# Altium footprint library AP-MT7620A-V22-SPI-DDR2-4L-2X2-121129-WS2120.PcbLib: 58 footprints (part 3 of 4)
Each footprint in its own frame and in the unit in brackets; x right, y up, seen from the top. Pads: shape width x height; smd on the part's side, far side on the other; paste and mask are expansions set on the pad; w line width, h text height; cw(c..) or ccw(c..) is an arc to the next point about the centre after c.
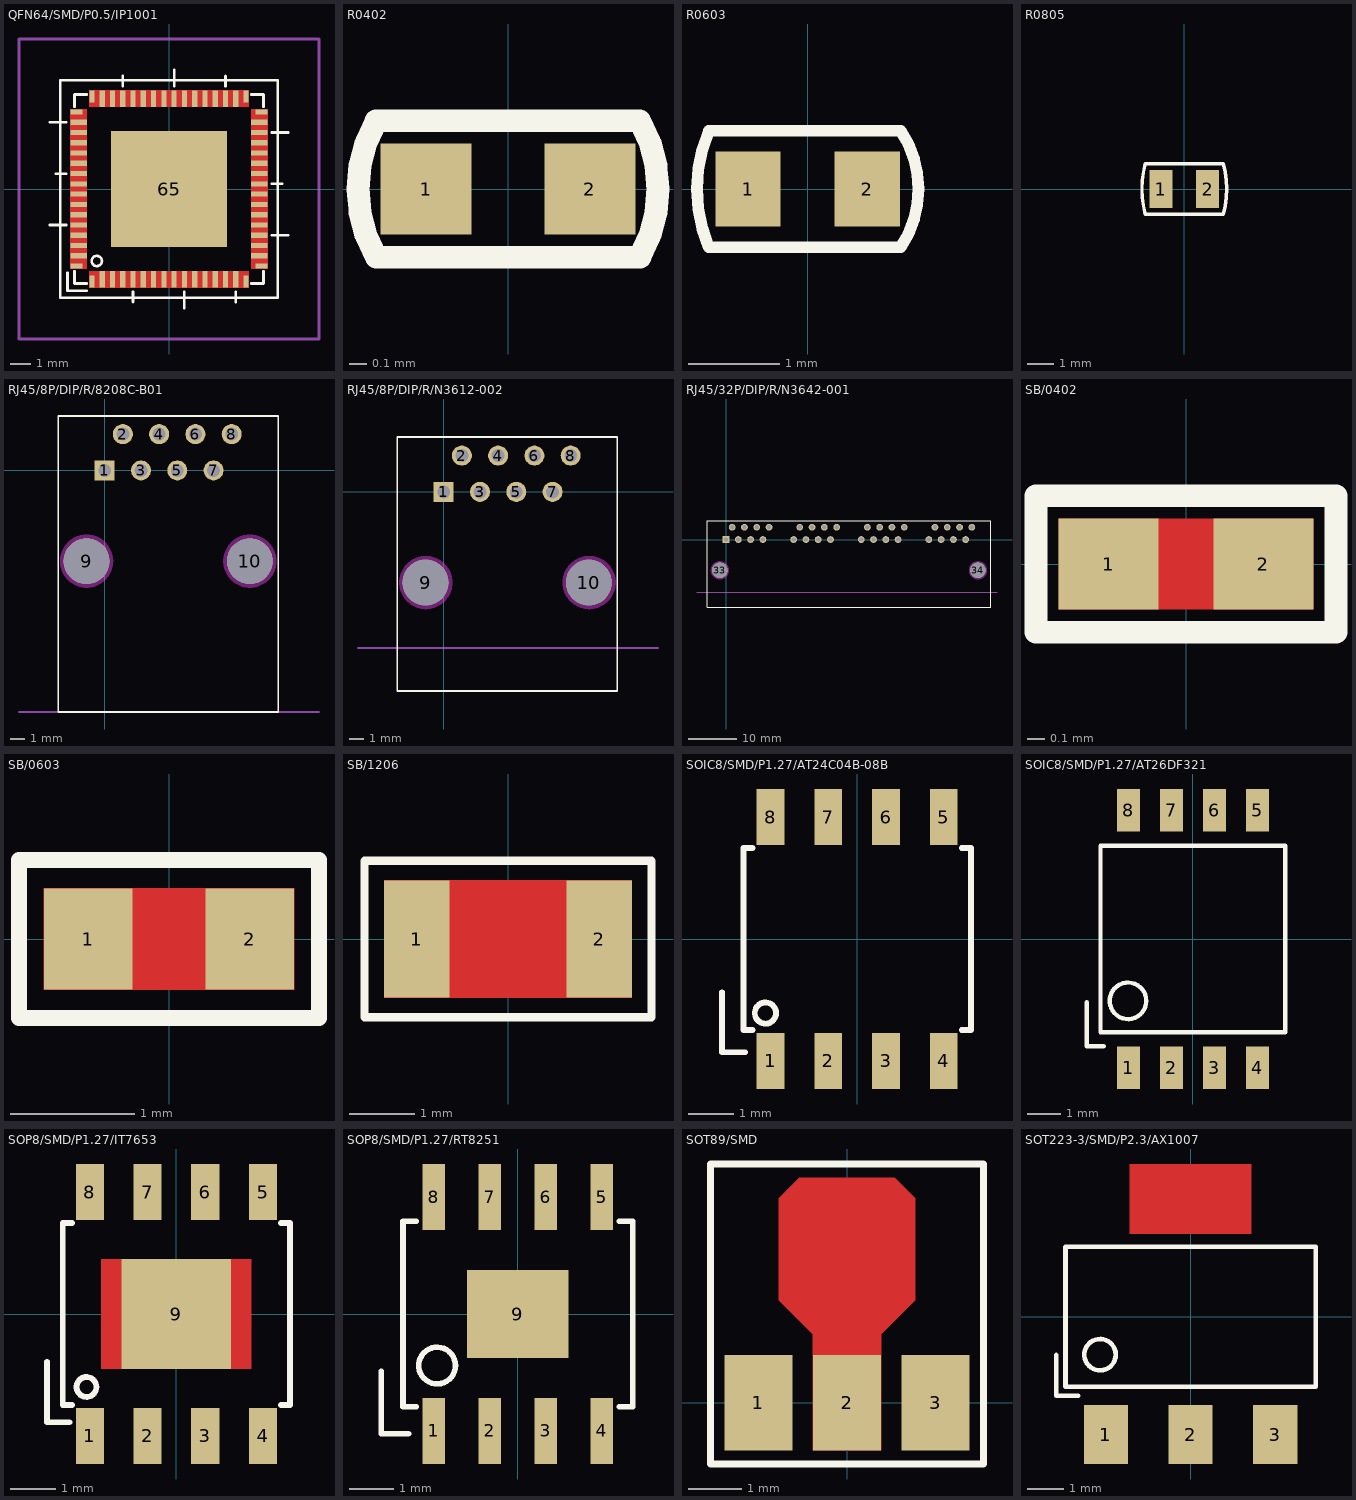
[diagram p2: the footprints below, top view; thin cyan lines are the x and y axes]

## QFN64/SMD/P0.5/IP1001 [mm]
pads (65):
  rect 0.25x0.6 smd: 1(-3.75,-4.5) 16(3.75,-4.5) 33(3.75,4.5) 48(-3.75,4.5)
  rect 0.25x0.8 smd: 2(-3.25,-4.4) 3(-2.75,-4.4) 4(-2.25,-4.4) 5(-1.75,-4.4) 6(-1.25,-4.4) 7(-0.75,-4.4) 8(-0.25,-4.4) 9(0.25,-4.4) 10(0.75,-4.4) 11(1.25,-4.4) 12(1.75,-4.4) 13(2.25,-4.4) 14(2.75,-4.4) 15(3.25,-4.4) 34(3.25,4.4) 35(2.75,4.4) 36(2.25,4.4) 37(1.75,4.4) 38(1.25,4.4) 39(0.75,4.4) 40(0.25,4.4) 41(-0.25,4.4) 42(-0.75,4.4) 43(-1.25,4.4) 44(-1.75,4.4) 45(-2.25,4.4) 46(-2.75,4.4) 47(-3.25,4.4)
  rect 0.6x0.25 smd: 17(4.5,-3.75) 32(4.5,3.75) 49(-4.5,3.75) 64(-4.5,-3.75)
  rect 0.8x0.25 smd: 18(4.4,-3.25) 19(4.4,-2.75) 20(4.4,-2.25) 21(4.4,-1.75) 22(4.4,-1.25) 23(4.4,-0.75) 24(4.4,-0.25) 25(4.4,0.25) 26(4.4,0.75) 27(4.4,1.25) 28(4.4,1.75) 29(4.4,2.25) 30(4.4,2.75) 31(4.4,3.25) 50(-4.4,3.25) 51(-4.4,2.75) 52(-4.4,2.25) 53(-4.4,1.75) 54(-4.4,1.25) 55(-4.4,0.75) 56(-4.4,0.25) 57(-4.4,-0.25) 58(-4.4,-0.75) 59(-4.4,-1.25) 60(-4.4,-1.75) 61(-4.4,-2.25) 62(-4.4,-2.75) 63(-4.4,-3.25)
  rect 5.64x5.64 smd: 65(0,0)
Top Layer:
  pour cut-out: 3.876,4 -3.876,4 -3.876,4.802 3.876,4.802
  pour cut-out: 3.87,-4.794 -3.882,-4.794 -3.882,-3.993 3.87,-3.993
  pour cut-out: 4.798,3.88 4.798,-3.872 3.993,-3.872 3.993,3.88
  pour cut-out: -3.998,3.877 -3.998,-3.88 -4.806,-3.88 -4.806,3.877
Top Overlay:
  circle w0.127: c-3.513,-3.503 r0.25
  lines w0.127: -5.8,-1.75 -5,-1.75 ; -5.8,3.25 -5,3.25 ; -5.5,0.75 -5,0.75 ; -4.939,-4.082 -4.939,-4.956 -4.012,-4.956 ; -4.6,-4 -4.6,-4.6 -4,-4.6 ; -4.6,4 -4.6,4.6 -4,4.6 ; -2.25,5 -2.25,5.5 ; -1.75,-5.5 -1.75,-5 ; 0.25,5 0.25,5.8 ; 0.75,-5.8 0.75,-5 ; 2.75,5 2.75,5.5 ; 3.25,-5.5 3.25,-5 ; 4,-4.6 4.6,-4.6 4.6,-4 ; 4,4.6 4.6,4.6 4.6,4 ; 5,-2.25 5.8,-2.25 ; 5,0.25 5.5,0.25 ; 5,2.75 5.8,2.75 ; -5.3,-5.3 5.3,-5.3 5.3,5.3 -5.3,5.3 -5.3,-5.3
Top Paste:
  region: 0.2,2.57 2.57,2.57 2.57,0.2 0.2,0.2
  region: -2.57,2.57 -0.2,2.57 -0.2,0.2 -2.57,0.2
  region: -2.57,-0.2 -0.2,-0.2 -0.2,-2.57 -2.57,-2.57
  region: 0.2,-0.2 2.57,-0.2 2.57,-2.57 0.2,-2.57
Mechanical 16:
  lines w0.127: -7.3,-7.3 7.3,-7.3 7.3,7.3 -7.3,7.3 -7.3,-7.3

## R0402 [mil]
pads (2):
  rect 20x20 smd: 1(-18,0) 2(18,0)
Top Overlay:
  lines w5: -29.02,14.97 ccw(c-2.88,0) -28.99,-15.02 29,-15 ; -29,15 29,15 cw(c2.88,0) 29.02,-14.97

## R0603 [mil]
pads (2):
  rect 28x32 smd: 1(-25.59,0) 2(25.59,0)
Top Overlay:
  lines w5: -42.5,-25 40,-25 ccw(c2.5,0) 40,25.01 -42.5,25 ; -42.51,-24.97 cw(c16.88,0) -42.47,25.07

## R0805 [mil]
pads (2):
  rect 34x56 smd: 1(-34.45,0) 2(34.45,0)
Top Overlay:
  lines w5: -57.49,-37.53 cw(c80.62,0) -57.49,37.53 ; -57.5,-37.5 57.5,-37.5 ; -57.5,37.5 57.5,37.5 ; 57.47,37.6 cw(c-78.12,0) 57.54,-37.37

## RJ45/8P/DIP/R/8208C-B01 [mm]
pads (10):
  rect 1.4x1.4 / inner round 1.4 / far side rect 1.4x1.4 hole 0.9: 1(0,0)
  round 1.4 hole 0.9: 2(1.27,2.54) 3(2.54,0) 4(3.81,2.54) 5(5.08,0) 6(6.35,2.54) 7(7.62,0) 8(8.89,2.54)
  round 3.2 hole 3.2 unplated: 9(-1.27,-6.35) 10(10.16,-6.35)
Top Overlay:
  lines w0.127: -3.255,-16.9 12.145,-16.9 12.145,3.8 -3.255,3.8 -3.255,-16.9
Keep-Out Layer:
  drawing of 2 lines, arcs and shapes, not listed
Mechanical 16:
  lines w0.127: -6,-16.9 15,-16.9

## RJ45/8P/DIP/R/N3612-002 [mm]
pads (10):
  rect 1.4x1.4 / inner round 1.4 / far side rect 1.4x1.4 hole 0.9: 1(0,0)
  round 1.4 hole 0.9: 2(1.27,2.54) 3(2.54,0) 4(3.81,2.54) 5(5.08,0) 6(6.35,2.54) 7(7.62,0) 8(8.89,2.54)
  round 3.2 hole 3.2 unplated: 9(-1.27,-6.35) 10(10.16,-6.35)
Top Overlay:
  lines w0.127: -3.255,-13.95 12.145,-13.95 12.145,3.85 -3.255,3.85 -3.255,-13.95
Keep-Out Layer:
  drawing of 2 lines, arcs and shapes, not listed
Mechanical 16:
  lines w0.127: -6,-10.922 15,-10.922

## RJ45/32P/DIP/R/N3642-001 [mm]
pads (34):
  rect 1.4x1.4 / inner round 1.4 / far side round 1.4 hole 0.9: 1(0,0)
  round 1.4 hole 0.9: 2(1.27,2.54) 3(2.54,0) 4(3.81,2.54) 5(5.08,0) 6(6.35,2.54) 7(7.62,0) 8(8.89,2.54) 9(13.97,0) 10(15.24,2.54) 11(16.51,0) 12(17.78,2.54) 13(19.05,0) 14(20.32,2.54) 15(21.59,0) 16(22.86,2.54) 17(27.94,0) 18(29.21,2.54) 19(30.48,0) 20(31.75,2.54) 21(33.02,0) 22(34.29,2.54) 23(35.56,0) 24(36.83,2.54) 25(41.91,0) 26(43.18,2.54) 27(44.45,0) 28(45.72,2.54) 29(46.99,0) 30(48.26,2.54) 31(49.53,0) 32(50.8,2.54)
  round 3.2 hole 3.2 unplated: 33(-1.27,-6.35) 34(52.07,-6.35)
Top Overlay:
  lines w0.127: -3.9,-13.95 54.7,-13.95 54.7,3.85 -3.9,3.85 -3.9,-13.95
Keep-Out Layer:
  drawing of 2 lines, arcs and shapes, not listed
Mechanical 16:
  lines w0.127: -6,-10.922 56,-10.922

## SB/0402 [mil]
pads (2):
  rect 22x20 smd: 1(-17,0) 2(17,0)
Top Layer:
  region: -28,10 0,10 0,-10 -28,-10
  region: 28,-10 0,-10 0,10 28,10
Top Overlay:
  lines w5: -33,-15 -33,15 33,15 33,-15 -33,-15

## SB/0603 [mil]
pads (2):
  rect 28x32 smd: 1(-25.59,0) 2(25.59,0)
Top Layer:
  region: 0,16 39.6,16 39.6,-16 0,-16
  region: -39.6,16 0,16 0,-16 -39.6,-16
Top Overlay:
  lines w5: -47.5,-25 47.5,-25 47.5,25 -47.5,25 -47.5,-25

## SB/1206 [mm]
pads (2):
  rect 1x1.8 smd: 1(-1.4,0) 2(1.4,0)
Top Layer:
  region: -1.9,0.9 0,0.9 0,-0.9 -1.9,-0.9
  region: 0,-0.9 1.9,-0.9 1.9,0.9 0,0.9
Top Overlay:
  lines w0.127: -2.2,-1.2 2.2,-1.2 2.2,1.2 -2.2,1.2 -2.2,-1.2

## SOIC8/SMD/P1.27/AT24C04B-08B [mm]
pads (8):
  rect 0.61x1.235 smd: 1(-1.905,-2.68) 2(-0.635,-2.68) 3(0.635,-2.68) 4(1.905,-2.68) 5(1.905,2.68) 6(0.635,2.68) 7(-0.635,2.68) 8(-1.905,2.68)
Top Overlay:
  circle w0.127: c-2.018,-1.628 r0.233
  lines w0.127: -2.972,-1.168 -2.972,-2.489 -2.464,-2.489 ; -2.3,-2 -2.5,-2 -2.5,2 -2.3,2 ; 2.3,-2 2.5,-2 2.5,2 2.3,2

## SOIC8/SMD/P1.27/AT26DF321 [mm]
pads (8):
  rect 0.68x1.25 smd: 1(-1.905,-3.805) 2(-0.635,-3.805) 3(0.635,-3.805) 4(1.905,-3.805) 5(1.905,3.805) 6(0.635,3.805) 7(-0.635,3.805) 8(-1.905,3.805)
Top Overlay:
  circle w0.127: c-1.915,-1.826 r0.541
  lines w0.127: -3.13,-1.867 -3.13,-3.167 -2.63,-3.167 ; -2.725,-2.75 2.725,-2.75 2.725,2.75 -2.725,2.75 -2.725,-2.75

## SOP8/SMD/P1.27/IT7653 [mm]
pads (9):
  rect 0.62x1.235 smd: 1(-1.905,-2.682) 2(-0.635,-2.682) 3(0.635,-2.682) 4(1.905,-2.682) 5(1.905,2.682) 6(0.635,2.682) 7(-0.635,2.682) 8(-1.905,2.682)
  rect 2.41x2.41 smd: 9(0,0)
Top Layer:
  region: -1.65,1.205 1.65,1.205 1.65,-1.205 -1.65,-1.205
Top Overlay:
  circle w0.127: c-1.979,-1.605 r0.218
  lines w0.127: -2.85,-1.05 -2.85,-2.384 -2.35,-2.384 ; -2.3,-2 -2.5,-2 -2.5,2 -2.3,2 ; 2.3,-2 2.5,-2 2.5,2 2.3,2
Top Paste:
  region: 0.2,0.955 1.4,0.955 1.4,-0.955 0.2,-0.955
  region: -1.4,0.955 -0.2,0.955 -0.2,-0.955 -1.4,-0.955

## SOP8/SMD/P1.27/RT8251 [mm]
pads (9):
  rect 0.51x1.5 smd: 1(-1.905,-2.65) 2(-0.635,-2.65) 3(0.635,-2.65) 4(1.905,-2.65) 5(1.905,2.65) 6(0.635,2.65) 7(-0.635,2.65) 8(-1.905,2.65)
  rect 2.3x2 smd: 9(0,0)
Top Overlay:
  circle w0.127: c-1.829,-1.168 r0.416
  lines w0.127: -3.099,-1.295 -3.099,-2.718 -2.476,-2.718 ; -2.3,-2.1 -2.602,-2.1 -2.602,2.1 -2.3,2.1 ; 2.3,-2.1 2.602,-2.1 2.602,2.1 2.3,2.1

## SOT89/SMD [mil]
pads (3):
  rect 50x70 smd: 1(-65,0) 2(0,0) 3(65,0)
Top Layer:
  region: 25,-35 25,50 50,75 50,150 35,165 -35,165 -50,150 -50,75 -25,50 -25,-35
Top Overlay:
  lines w5: -100,-45 100,-45 100,175 -100,175 -100,-45

## SOT223-3/SMD/P2.3/AX1007 [mm]
pads (3):
  rect 1.2x1.6 smd: 1(-2.3,-3.2) 2(0,-3.2) 3(2.3,-3.2)
Top Layer:
  region: -1.65,4.15 1.65,4.15 1.65,2.25 -1.65,2.25
Top Overlay:
  circle w0.127: c-2.46,-1.03 r0.426
  lines w0.127: -3.65,-1.04 -3.65,-2.15 -3.05,-2.15 ; -3.4,-1.9 3.4,-1.9 3.4,1.9 -3.4,1.9 -3.4,-1.9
